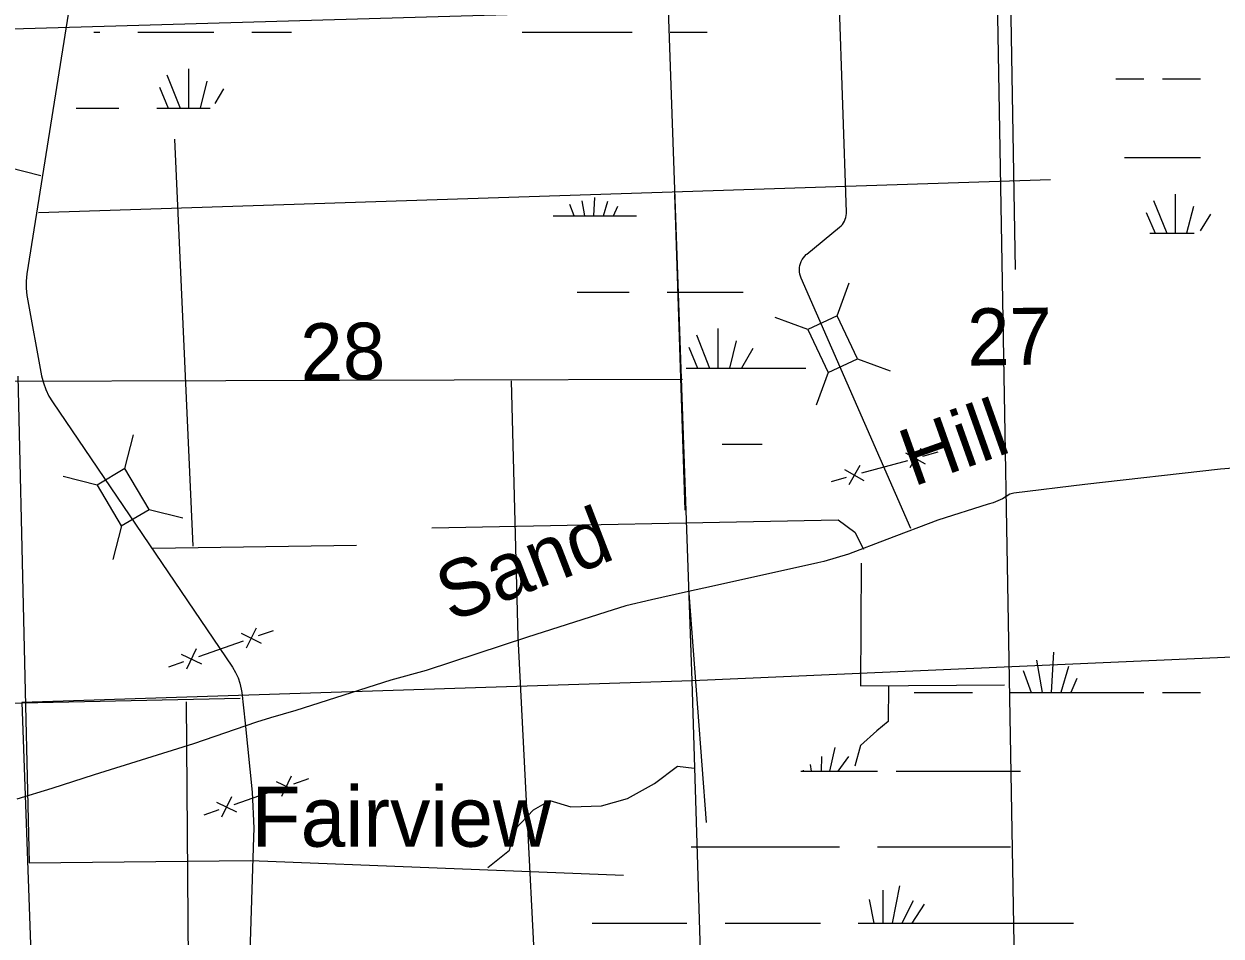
# Model space of a CAD drawing. Extents: x 2480962 to 2688785, y 277103 to 599240.
# Drawn here: x 2590907 to 2600353, y 533213 to 540409 of the extents above; entities that cross this region are included whole.
import ezdxf

# ---------------------------------------------------------------- set-up
doc = ezdxf.new("R2010")
doc.units = 0
for name, color, linetype in [('Communities and Subdivisions Names without Post Office', 7, 'Continuous'), ('Divided_Highway', 7, 'Continuous'), ('Local Roads Improved', 7, 'Continuous'), ('Local Roads Related Text', 7, 'Continuous'), ('Section Lines', 7, 'Continuous'), ('Section Numbers', 7, 'Continuous'), ('Swamps', 7, 'Continuous'), ('Uninventoried Roads and Features', 7, 'Continuous')]:
    doc.layers.add(name, color=color, linetype=linetype)

msp = doc.modelspace()

# ---------------------------------------------------------------- linework, layer by layer
at = {"layer": 'Divided_Highway'}
msp.add_line((2599203.547, 505666.246), (2598405.641, 551119.704), dxfattribs=at)
at = {"layer": 'Local Roads Improved'}
msp.add_lwpolyline([(2600514.054, 536910.929), (2600349.24, 536897.565), (2599277.943, 536775.068), (2598718.91, 536706.024), (2598685.501, 536699.342), (2598627.593, 536663.706), (2598554.095, 536630.298), (2598516.232, 536619.162), (2598117.558, 536494.437), (2597716.657, 536340.758), (2597413.755, 536224.943), (2597217.759, 536169.262), (2597170.987, 536158.126), (2596355.822, 535975.493), (2596126.418, 535926.494), (2595859.15, 535866.359), (2595656.473, 535817.36), (2595498.34, 535768.361), (2594881.398, 535570.138), (2594081.823, 535309.552), (2593801.193, 535231.6), (2593052.845, 534993.286), (2592852.394, 534935.378), (2592741.033, 534899.743), (2592244.361, 534730.474), (2591460.377, 534485.479), (2591126.293, 534378.572), (2590850.117, 534293.937)], dxfattribs=at)
at = {"layer": 'Section Lines'}
for p, q in [((2590722.429, 540367.883), (2595992.413, 540520.393)), ((2596180.842, 535227.487), (2595992.413, 540520.393)), ((2601464.223, 535459.507), (2596180.842, 535227.487)), ((2596180.842, 535227.487), (2590889.135, 535054.66)), ((2596338.07, 529921.695), (2596180.842, 535227.487)), ((2590889.135, 535054.66), (2591081.271, 529756.917))]:
    msp.add_line(p, q, dxfattribs=at)
at = {"layer": 'Swamps'}
for p, q in [((2591806.268, 540343.505), (2592406.268, 540343.514)), ((2592204.931, 540054.516), (2592204.934, 539743.513)), ((2592035.779, 540006.185), (2592138.8, 539743.512)), ((2592349.919, 539957.861), (2592296.309, 539743.414)), ((2591975.369, 539909.526), (2592046.182, 539743.511)), ((2595982.927, 538294.035), (2596582.927, 538294.044)), ((2596212.438, 537956.715), (2596315.458, 537694.043)), ((2596381.589, 538005.046), (2596381.592, 537694.044)), ((2596152.028, 537860.057), (2596222.84, 537694.041)), ((2596526.577, 537908.391), (2596472.967, 537693.944)), ((2596659.483, 537847.982), (2596569.764, 537694.175))]:
    msp.add_line(p, q, dxfattribs=at)
for points in [[(2591459.191, 540343.5), (2591506.268, 540343.501)], [(2592706.268, 540343.518), (2593017.294, 540343.523)], [(2594837.323, 540343.549), (2595706.269, 540343.562)], [(2596006.269, 540343.566), (2596298.321, 540343.571)], [(2599523.619, 539974.531), (2599742.62, 539974.54)], [(2599891.12, 539974.546), (2600191.621, 539974.558)], [(2592482.824, 539897.452), (2592414.391, 539780.133)], [(2591320.128, 539743.5), (2591656.275, 539743.505)], [(2591956.275, 539743.51), (2592375.205, 539743.516)], [(2599590.376, 539354.723), (2600191.628, 539354.747)], [(2599991.38, 539065.24), (2599991.384, 538757.179)], [(2595248.355, 538894.193), (2595213.603, 538985.416)], [(2595333.429, 538894.105), (2595311.912, 539012.446)], [(2595404.429, 538894.057), (2595412.392, 539040.072)], [(2595481.115, 538894.236), (2595514.45, 539010.907)], [(2595557.711, 538894.159), (2595592.179, 538970.755)], [(2599820.63, 539016.983), (2599924.383, 538757.176)], [(2595082.92, 538894.02), (2595740.713, 538894.029)], [(2599761.131, 538920.481), (2599831.633, 538757.172)], [(2600136.132, 538968.746), (2600080.384, 538757.182)], [(2600269.633, 538909.376), (2600187.884, 538775.748)], [(2599790.883, 538757.171), (2599831.633, 538757.172)], [(2599831.633, 538757.172), (2599924.383, 538757.176)], [(2599924.383, 538757.176), (2599991.384, 538757.179)], [(2599991.384, 538757.179), (2600080.384, 538757.182)], [(2600080.384, 538757.182), (2600139.634, 538757.184)], [(2595272.603, 538294.025), (2595682.927, 538294.031)], [(2596132.933, 537694.04), (2597076.235, 537694.054)], [(2596414.957, 537094.047), (2596732.94, 537094.051)], [(2598896.417, 535390.897), (2598940.92, 535134.837)], [(2599029.917, 535454.027), (2599011.421, 535134.84)], [(2598792.418, 535309.268), (2598855.67, 535134.834)], [(2599148.669, 535338.969), (2599089.421, 535134.843)], [(2599215.67, 535246.16), (2599167.421, 535134.846)], [(2597931.42, 535134.816), (2598391.67, 535134.823)], [(2598692.17, 535134.827), (2598855.67, 535134.834)], [(2598855.67, 535134.834), (2598940.92, 535134.837)], [(2598940.92, 535134.837), (2599011.421, 535134.84)], [(2599011.421, 535134.84), (2599089.421, 535134.843)], [(2599089.421, 535134.843), (2599167.421, 535134.846)], [(2599167.421, 535134.846), (2599742.673, 535134.868)], [(2599891.173, 535134.874), (2600191.674, 535134.885)], [(2597200.175, 534630.057), (2597196.677, 534514.996)], [(2597304.175, 534700.622), (2597263.427, 534514.997)], [(2597411.925, 534630.06), (2597330.177, 534514.998)], [(2597111.176, 534566.994), (2597118.677, 534514.995)], [(2597036.927, 534514.993), (2597055.427, 534514.994)], [(2597055.427, 534522.431), (2597055.427, 534514.994)], [(2597055.427, 534514.994), (2597118.677, 534514.995)], [(2597118.677, 534514.995), (2597196.677, 534514.996)], [(2597196.677, 534514.996), (2597263.427, 534514.997)], [(2597263.427, 534514.997), (2597330.177, 534514.998)], [(2597330.177, 534514.998), (2597641.927, 534515.002)], [(2597790.427, 534515.005), (2598770.177, 534515.021)], [(2596172.183, 533917.483), (2597341.183, 533917.5)], [(2597641.933, 533917.505), (2598692.183, 533917.457)], [(2597816.437, 533609.446), (2597756.94, 533316.259)], [(2597575.188, 533501.818), (2597612.19, 533316.257)], [(2597682.687, 533576.007), (2597682.69, 533316.258)], [(2597923.938, 533490.698), (2597834.94, 533316.26)], [(2598009.438, 533464.699), (2597912.94, 533316.261)], [(2595389.19, 533316.224), (2596138.69, 533316.235)], [(2596439.44, 533316.239), (2597192.94, 533316.251)], [(2597489.69, 533316.255), (2597612.19, 533316.257)], [(2597612.19, 533316.257), (2597682.69, 533316.258)], [(2597682.69, 533316.258), (2597756.94, 533316.259)], [(2597756.94, 533316.259), (2597834.94, 533316.26)], [(2597834.94, 533316.26), (2597912.94, 533316.261)], [(2597912.94, 533316.261), (2599189.691, 533316.228)]]:
    msp.add_lwpolyline(points, dxfattribs=at)
at = {"layer": 'Uninventoried Roads and Features'}
for p, q in [((2597396.358, 538923.512), (2597132.823, 546879.185)), ((2591343.212, 541033.916), (2590929.332, 538436.959)), ((2592094.089, 539501.013), (2592238.457, 536289.862)), ((2591022.29, 538922.077), (2599006.682, 539181.918)), ((2596040.716, 539064.322), (2596121.994, 536573.819)), ((2597084.312, 538593.017), (2597343.244, 538806.039)), ((2597905.746, 536428.003), (2597039.121, 538403.863)), ((2597324.866, 538106.659), (2597418.599, 538365.145)), ((2590931.708, 538252.705), (2591046.794, 537633.749)), ((2597092.98, 537998.192), (2596834.494, 538091.925)), ((2597324.866, 538106.659), (2597092.98, 537998.192)), ((2597483.752, 537766.982), (2597324.866, 538106.659)), ((2597092.98, 537998.192), (2597251.866, 537658.515)), ((2597251.866, 537658.515), (2597483.752, 537766.982)), ((2597483.752, 537766.981), (2597742.238, 537673.248)), ((2597252.513, 537660.299), (2597158.78, 537401.813)), ((2589580.69, 537586.196), (2596103.673, 537606.231)), ((2594752.603, 537594.664), (2594803.711, 535570.689)), ((2591131.872, 537426.772), (2592551.969, 535333.785)), ((2591703.561, 536901.763), (2591771.306, 537168.242)), ((2597863.523, 537026.474), (2598017.265, 536939.218)), ((2597984.022, 537059.717), (2597896.766, 536905.975)), ((2598000.643, 536999.467), (2598121.142, 537032.71)), ((2591703.561, 536901.763), (2591483.521, 536770.924)), ((2591895.219, 536579.44), (2591703.561, 536901.763)), ((2597381.528, 536893.501), (2597535.269, 536806.246)), ((2597502.026, 536926.745), (2597414.771, 536773.003)), ((2597518.648, 536866.495), (2597880.145, 536966.224)), ((2591483.521, 536770.924), (2591217.042, 536838.669)), ((2597277.65, 536800.009), (2597398.149, 536833.252)), ((2591483.521, 536770.924), (2591675.179, 536448.601)), ((2591675.179, 536448.601), (2591895.219, 536579.44)), ((2591895.218, 536579.439), (2592161.698, 536511.695)), ((2591675.647, 536450.44), (2591607.902, 536183.961)), ((2591924.618, 536273.487), (2593531.815, 536296.331)), ((2596152.724, 535918.115), (2596289.39, 534110.255)), ((2592620.18, 535601.54), (2592779.237, 535524.396)), ((2592738.28, 535642.496), (2592661.136, 535483.44)), ((2592758.758, 535583.446), (2592876.859, 535624.402)), ((2592265.88, 535478.672), (2592188.736, 535319.615)), ((2592286.358, 535419.622), (2592640.658, 535542.49)), ((2592147.78, 535437.715), (2592306.836, 535360.572)), ((2592050.158, 535337.709), (2592168.258, 535378.665)), ((2592626.147, 535133.669), (2592653.654, 534893.013)), ((2592186.183, 535060.959), (2592208.698, 532362.635)), ((2592653.654, 534893.013), (2592706.992, 534348.75)), ((2593016.39, 534474.501), (2592939.246, 534315.445)), ((2593036.868, 534415.451), (2593154.969, 534456.407)), ((2592564.468, 534251.627), (2592918.768, 534374.495)), ((2592898.29, 534433.545), (2593057.347, 534356.401)), ((2592425.89, 534269.72), (2592584.946, 534192.577)), ((2592543.99, 534310.677), (2592466.846, 534151.62)), ((2592328.268, 534169.714), (2592446.368, 534210.67)), ((2592718.507, 533994.648), (2592613.798, 530790.964))]:
    msp.add_line(p, q, dxfattribs=at)
for points in [[(2595746.656, 546870.661), (2595744.167, 545986.449), (2595666.881, 545911.436), (2595642.474, 545800.876), (2595742.901, 545710.364), (2595801.606, 545673.012), (2595846.166, 544424.948), (2598467.6, 544519.71), (2598669.502, 542394.722), (2598677.735, 542124.632), (2598606.17, 541804.568), (2598579.316, 541551.1), (2598668.374, 541369.614), (2598682.974, 541074.565), (2598728.328, 538471.323)], [(2586865.379, 540112.142), (2587812.101, 540017.391), (2588095.662, 539926.942), (2588057.573, 539576.709), (2588111.44, 539168.602), (2588129.782, 539043.514), (2588289.084, 538990.942), (2588794.743, 539048.105), (2589364.121, 539100.841), (2589651.82, 539245.998), (2589783.821, 539289.366), (2589919.281, 539267.172), (2590066.932, 539218.211), (2590177.433, 539191.621), (2590301.592, 539240.612), (2590508.332, 539302.954), (2590617.843, 539318.814), (2590782.654, 539277.943), (2591040.536, 539213.97)], [(2597343.244, 538806.039), (2597354.511, 538816.343), (2597364.639, 538827.767), (2597373.518, 538840.19), (2597381.049, 538853.471), (2597387.151, 538867.466), (2597391.756, 538882.023), (2597394.814, 538896.981), (2597396.293, 538912.177), (2597396.358, 538923.512)], [(2597039.121, 538403.863), (2597033.163, 538419.643), (2597028.889, 538435.958), (2597026.343, 538452.63), (2597025.554, 538469.478), (2597026.53, 538486.316), (2597029.261, 538502.959), (2597033.715, 538519.226), (2597039.847, 538534.938), (2597047.587, 538549.922), (2597056.852, 538564.016), (2597067.538, 538577.064), (2597079.531, 538588.924), (2597084.312, 538593.017)], [(2590929.332, 538436.959), (2590923.351, 538380.582), (2590923.297, 538323.889), (2590929.169, 538267.501), (2590931.708, 538252.705)], [(2590859.706, 537629.036), (2590949.306, 533791.238), (2592697.337, 533809.376), (2595637.924, 533692.831)], [(2591046.794, 537633.749), (2591060.182, 537578.122), (2591079.313, 537524.201), (2591103.975, 537472.574), (2591131.872, 537426.772)], [(2594126.185, 536434.544), (2597332.467, 536497.432), (2597463.903, 536399.862), (2597530.684, 536264.229)], [(2597513.985, 536153.835), (2597507.651, 535186.53), (2598644.806, 535195.444)], [(2594803.711, 535570.689), (2595006.516, 531590.53), (2594899.077, 531485.913), (2594870.726, 531379.13), (2594872.784, 531043.272), (2594941.042, 530926.974), (2595029.189, 530867.088), (2595071.476, 529881.519)], [(2592551.969, 535333.785), (2592576.164, 535293.766), (2592596.045, 535251.435), (2592611.391, 535207.258), (2592622.036, 535161.721), (2592626.147, 535133.669)], [(2597727.438, 535185.447), (2597726.263, 534905.502), (2597635.445, 534832.129), (2597507.037, 534717.412), (2597462.652, 534554.301)], [(2592613.521, 535087.487), (2589538.396, 535021.616), (2589547.692, 534128.005)], [(2594566.585, 533754.823), (2594736.93, 533889.744), (2594779.389, 534052.814), (2594927.999, 534210.436), (2595055.472, 534282.663), (2595222.435, 534232.186), (2595463.191, 534241.204), (2595668.094, 534299.647), (2595883.162, 534418.152), (2596065.068, 534553.321), (2596196.539, 534536.832)], [(2592706.992, 534348.75), (2592719.891, 534064.365), (2592718.507, 533994.648)]]:
    msp.add_lwpolyline(points, dxfattribs=at)

# ---------------------------------------------------------------- texts
at = {"layer": 'Communities and Subdivisions Names without Post Office'}
msp.add_text('Fairview', height=475, rotation=0.0008444, dxfattribs=at).set_placement((2592702.348, 533918.128))
at = {"layer": 'Local Roads Related Text'}
for s, rotation, p in [('Hill', 19.5884944, (2597923.001, 536756.479)), ('Sand', 21.1034806, (2594274.122, 535687.281))]:
    msp.add_text(s, height=450, rotation=rotation, dxfattribs=at).set_placement(p)
at = {"layer": 'Section Numbers'}
for s, rotation, p in [('27', 0.8228472, (2598352.732, 537712.922)), ('28', 0.8220111, (2593091.027, 537594.956))]:
    msp.add_text(s, height=450, rotation=rotation, dxfattribs=at).set_placement(p)

doc.saveas('drawing.dxf')
